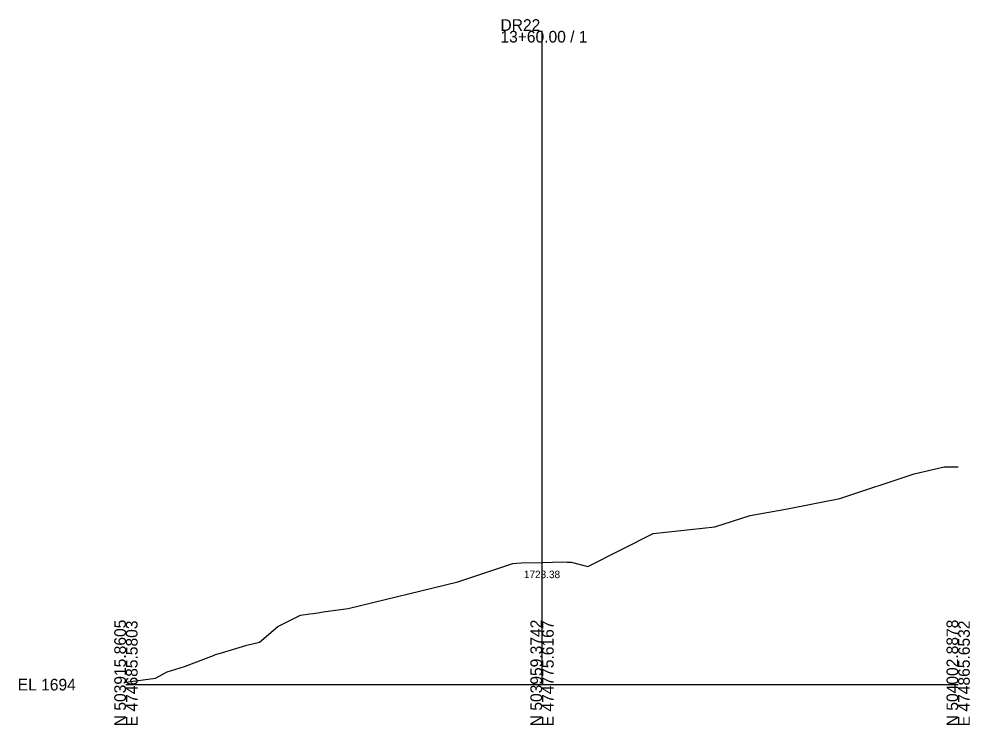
# Model space of a CAD drawing. Extents: x -26 to 1203, y -10 to 9633.
# Drawn here: x -25.7 to 202.8, y 8990.3 to 9159.9 of the extents above; entities that cross this region are included whole.
import ezdxf

# ---------------------------------------------------------------- set-up
doc = ezdxf.new("R2010")
doc.units = 0
for name, color, linetype in [('Exist Cross Section Cell', 7, 'Continuous'), ('Exist XS Center Line Elevation Label', 7, 'Continuous'), ('Exist XS Ground Line', 7, 'Continuous'), ('Scratch_Level_5', 7, 'Continuous')]:
    doc.layers.add(name, color=color, linetype=linetype)

msp = doc.modelspace()

# ---------------------------------------------------------------- linework, layer by layer
at = {"layer": 'Exist Cross Section Cell'}
for p, q in [((100, 9000), (100, 9157.07)), ((0, 9000), (100, 9000)), ((100, 9000), (200, 9000))]:
    msp.add_line(p, q, dxfattribs=at)
at = {"layer": 'Exist XS Ground Line'}
msp.add_lwpolyline([(0, 9000.56), (7.07, 9001.52), (9.9, 9003.09), (14.07, 9004.36), (21.01, 9006.98), (21.56, 9007.2), (22.69, 9007.52), (29.05, 9009.5), (32.12, 9010.24), (36.54, 9013.98), (41.96, 9016.65), (42.53, 9016.73), (43.75, 9016.91), (44.23, 9016.99), (44.99, 9017.1), (46.1, 9017.27), (46.59, 9017.34), (47.39, 9017.46), (47.93, 9017.54), (53.4, 9018.32), (79.79, 9024.72), (93, 9029.12), (93.98, 9029.2), (95, 9029.28), (100, 9029.38), (105, 9029.48), (106.02, 9029.44), (107, 9029.4), (111, 9028.4), (126.74, 9036.27), (141.52, 9037.9), (150, 9040.6), (158.97, 9042.26), (171.58, 9044.72), (189.42, 9050.68), (196.67, 9052.34), (200, 9052.36)], dxfattribs=at)
at = {"layer": 'Scratch_Level_5'}
msp.add_lwpolyline([(0, 9000.56), (7.07, 9001.52), (9.9, 9003.09), (14.07, 9004.36), (21.01, 9006.98), (21.56, 9007.2), (22.69, 9007.52), (29.05, 9009.5), (32.12, 9010.24), (36.54, 9013.98), (41.96, 9016.65), (42.53, 9016.73), (43.75, 9016.91), (44.23, 9016.99), (44.99, 9017.1), (46.1, 9017.27), (46.59, 9017.34), (47.39, 9017.46), (47.93, 9017.54), (53.4, 9018.32), (79.79, 9024.72), (93, 9029.12), (93.98, 9029.2), (95, 9029.28), (100, 9029.38), (105, 9029.48), (106.02, 9029.44), (107, 9029.4), (111, 9028.4), (126.74, 9036.27), (141.52, 9037.9), (150, 9040.6), (158.97, 9042.26), (171.58, 9044.72), (189.42, 9050.68), (196.67, 9052.34), (200, 9052.36)], dxfattribs=at)

# ---------------------------------------------------------------- texts
at = {"layer": 'Exist Cross Section Cell'}
for s, p in [('DR22', (90, 9157.07)), ('13+60.00 / 1', (90, 9154.27)), ('EL 1694', (-26, 8998.6))]:
    msp.add_text(s, height=2.8, dxfattribs=at).set_placement(p)
for s, p in [('N 503915.8605', (0, 8990)), ('E 474685.5803', (2.8, 8990)), ('N 503959.3742', (100, 8990)), ('E 474775.6167', (102.8, 8990)), ('N 504002.8878', (200, 8990)), ('E 474865.6532', (202.8, 8990))]:
    msp.add_text(s, height=2.8, rotation=90, dxfattribs=at).set_placement(p)
at = {"layer": 'Exist XS Center Line Elevation Label'}
msp.add_text('1723.38', height=1.8, dxfattribs=at).set_placement((95.64, 9025.58))

doc.saveas('drawing.dxf')
